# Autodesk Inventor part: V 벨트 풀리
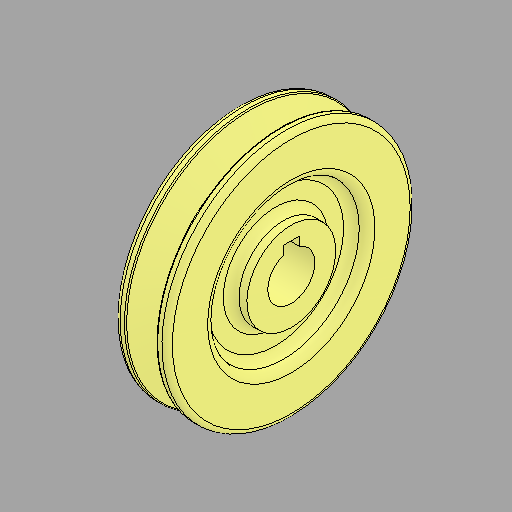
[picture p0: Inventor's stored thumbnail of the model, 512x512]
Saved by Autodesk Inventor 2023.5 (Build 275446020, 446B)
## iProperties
Created: 2025-07
Part Number: V 벨트 풀리
Material: 강철, 주조
Document SubType Name: Modeling
Designer: 1강의실14
Density: 7.85 g/cm^3
Appearance: 기본값
Author: jhkim
Sending System: Autodesk Inventor 2026
Preprocessor: ST-DEVELOPER v20.1
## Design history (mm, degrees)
feature "솔리드1"
node "솔리드2"
